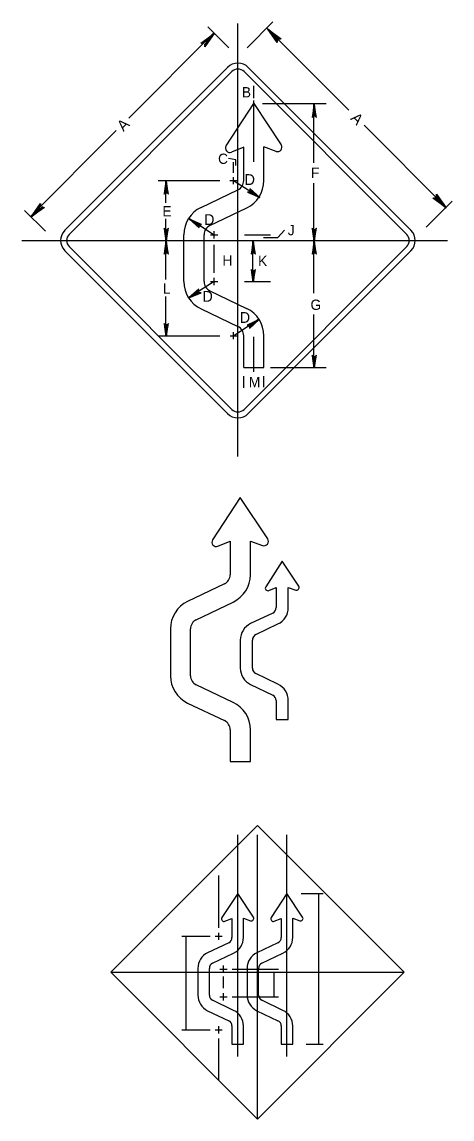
# Model space of a CAD drawing. Extents: x -0.124 to 0.191, y 0.004 to 0.276.
# Drawn here: x -0.1242 to -0.0247, y 0.0223 to 0.2759 of the extents above; entities that cross this region are included whole.
import ezdxf

# ---------------------------------------------------------------- set-up
doc = ezdxf.new("R2010")
doc.units = 0
doc.layers.add('1', color=7, linetype='Continuous')
doc.layers.add('3', color=7, linetype='Continuous')

# ---------------------------------------------------------------- blocks, each defined once
blk = doc.blocks.new('RARROW')
at = {"layer": '3'}
for p, q in [((-2.156, 0.28500000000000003), (-2.2665, 0.384625)), ((-2.2665, 0.384625), (0, 0)), ((0, 0), (-2.2665, -0.379125)), ((-2.156, 0.28500000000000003), (-2.075625, 0.12075)), ((0, 0), (-2.156, 0.28500000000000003)), ((-2.14975, -0.2705), (0, 0)), ((-2.075625, 0.12075), (0, 0)), ((0, 0), (-2.074, -0.108)), ((-2.2665, -0.379125), (-2.14975, -0.2705)), ((-2.074, -0.108), (-2.14975, -0.2705))]:
    blk.add_line(p, q, dxfattribs=at)

msp = doc.modelspace()

# ---------------------------------------------------------------- linework, layer by layer
at = {"layer": '1'}
for p, q in [((-0.07700190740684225, 0.24730114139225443), (-0.07061497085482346, 0.25708159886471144)), ((-0.07061497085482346, 0.25708159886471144), (-0.06426636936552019, 0.2475136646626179)), ((-0.07294829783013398, 0.24701153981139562), (-0.07577967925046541, 0.24583179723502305)), ((-0.07294829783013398, 0.23925057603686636), (-0.07294829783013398, 0.24701153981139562)), ((-0.06828164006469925, 0.23925057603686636), (-0.06828164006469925, 0.2470404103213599)), ((-0.06544031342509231, 0.24602565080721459), (-0.06828164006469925, 0.2470404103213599)), ((-0.07612017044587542, 0.23924826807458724), (-0.07445350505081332, 0.23924826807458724)), ((-0.07528683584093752, 0.23841493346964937), (-0.07528683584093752, 0.24008159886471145)), ((-0.08280441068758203, 0.23306196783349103), (-0.07427404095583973, 0.23714601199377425)), ((-0.08078922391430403, 0.22885283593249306), (-0.0722588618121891, 0.2329368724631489)), ((-0.08678163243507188, 0.2159133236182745), (-0.08678163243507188, 0.22674826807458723)), ((-0.08211496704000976, 0.21591331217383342), (-0.08211496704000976, 0.22674827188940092)), ((-0.08061496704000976, 0.22674826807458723), (-0.07894830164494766, 0.22674826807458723)), ((-0.07978163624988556, 0.22591493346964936), (-0.07978163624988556, 0.22758159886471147)), ((-0.08061496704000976, 0.21591493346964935), (-0.07894830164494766, 0.21591493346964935)), ((-0.07978163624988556, 0.21508159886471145), (-0.07978163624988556, 0.21674826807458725)), ((-0.08078842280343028, 0.21380836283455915), (-0.07226127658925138, 0.20972987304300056)), ((-0.08280199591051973, 0.20959846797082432), (-0.07427484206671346, 0.20551997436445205)), ((-0.07611478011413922, 0.20341493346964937), (-0.07444811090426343, 0.20341493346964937)), ((-0.07528144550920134, 0.20258159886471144), (-0.07528144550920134, 0.20424826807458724)), ((-0.07294829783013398, 0.19608159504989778), (-0.07294829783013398, 0.2034150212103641)), ((-0.06828164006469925, 0.19608159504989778), (-0.06828164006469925, 0.2034150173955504)), ((-0.07294829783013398, 0.19608159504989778), (-0.06828164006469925, 0.19608159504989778)), ((-0.07373907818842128, 0.1659831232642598), (-0.08012601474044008, 0.15620266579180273)), ((-0.06739047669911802, 0.1564151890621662), (-0.07373907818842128, 0.1659831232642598)), ((-0.07890378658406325, 0.15473332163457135), (-0.0760724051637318, 0.15591306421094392)), ((-0.0760724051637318, 0.15591306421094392), (-0.0760724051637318, 0.1481521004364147)), ((-0.07140574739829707, 0.1481521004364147), (-0.07140574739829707, 0.15594193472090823)), ((-0.07140574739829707, 0.15594193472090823), (-0.06856442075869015, 0.1549271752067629)), ((-0.06403025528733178, 0.1512579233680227), (-0.06786241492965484, 0.14538964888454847)), ((-0.06022109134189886, 0.14551716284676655), (-0.06403025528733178, 0.1512579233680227)), ((-0.07739814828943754, 0.14604753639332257), (-0.08592851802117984, 0.14196349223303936)), ((-0.06712907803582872, 0.14450804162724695), (-0.0654302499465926, 0.1452158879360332)), ((-0.0654302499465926, 0.1452158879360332), (-0.0654302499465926, 0.14055930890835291)), ((-0.06263025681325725, 0.14055930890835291), (-0.06263025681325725, 0.14523321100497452)), ((-0.06263025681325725, 0.14523321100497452), (-0.06092545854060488, 0.14462435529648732)), ((-0.08391333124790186, 0.1377543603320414), (-0.07538296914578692, 0.14183839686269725)), ((-0.06622569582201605, 0.13929657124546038), (-0.0713439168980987, 0.13684614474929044)), ((-0.08990573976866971, 0.13564979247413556), (-0.08990573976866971, 0.12481484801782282)), ((-0.0852390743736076, 0.12481483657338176), (-0.0852390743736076, 0.13564979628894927)), ((-0.07013480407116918, 0.1343206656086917), (-0.0650165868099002, 0.13677108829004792)), ((-0.07373025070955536, 0.13305792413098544), (-0.07373025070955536, 0.12655695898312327)), ((-0.07093024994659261, 0.1265569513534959), (-0.07093024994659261, 0.13305792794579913)), ((-0.06501803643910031, 0.12284688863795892), (-0.07013432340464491, 0.1252939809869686)), ((-0.07538538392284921, 0.1186313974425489), (-0.08391253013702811, 0.12270988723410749)), ((-0.07134246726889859, 0.1227680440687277), (-0.0662261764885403, 0.12032094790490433)), ((-0.08592610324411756, 0.11849999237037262), (-0.07739894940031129, 0.11442149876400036)), ((-0.0654302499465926, 0.11905797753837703), (-0.0654302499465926, 0.11465792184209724)), ((-0.06263025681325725, 0.11465792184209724), (-0.06263025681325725, 0.11905797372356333)), ((-0.0654302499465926, 0.11465792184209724), (-0.06263025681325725, 0.11465792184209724)), ((-0.0760724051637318, 0.11231654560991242), (-0.0760724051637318, 0.10498311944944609)), ((-0.07140574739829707, 0.10498311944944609), (-0.07140574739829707, 0.11231654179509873)), ((-0.0760724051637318, 0.10498311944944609), (-0.07140574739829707, 0.10498311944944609)), ((-0.07433316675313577, 0.07446970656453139), (-0.07797678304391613, 0.06889015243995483)), ((-0.07071141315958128, 0.06901139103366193), (-0.07433316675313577, 0.07446970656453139)), ((-0.06293316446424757, 0.07446970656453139), (-0.06657678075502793, 0.06889015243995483)), ((-0.059311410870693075, 0.06901139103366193), (-0.06293316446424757, 0.07446970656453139)), ((-0.07727952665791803, 0.06805191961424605), (-0.07566428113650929, 0.06872494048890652)), ((-0.07566428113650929, 0.06872494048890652), (-0.07566428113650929, 0.06429746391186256)), ((-0.07300204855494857, 0.06429746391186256), (-0.07300204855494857, 0.06874140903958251)), ((-0.07300204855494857, 0.06874140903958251), (-0.07138112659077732, 0.06816251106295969)), ((-0.06587952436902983, 0.06805191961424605), (-0.06426427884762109, 0.06872494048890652)), ((-0.06426427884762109, 0.06872494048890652), (-0.06426427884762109, 0.06429746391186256)), ((-0.06160204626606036, 0.06429746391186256), (-0.06160204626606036, 0.06874140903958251)), ((-0.06160204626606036, 0.06874140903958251), (-0.0599811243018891, 0.06816251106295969)), ((-0.0795664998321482, 0.06456970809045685), (-0.0778998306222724, 0.06456970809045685)), ((-0.07873316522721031, 0.06373637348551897), (-0.07873316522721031, 0.06540304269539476)), ((-0.07642059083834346, 0.06309685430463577), (-0.08128699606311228, 0.06076698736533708)), ((-0.06502058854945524, 0.06309685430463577), (-0.06988699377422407, 0.06076698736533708)), ((-0.08013737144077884, 0.058365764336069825), (-0.0752709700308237, 0.060695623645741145)), ((-0.06873736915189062, 0.058365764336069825), (-0.06387096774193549, 0.060695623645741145)), ((-0.08355592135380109, 0.05716514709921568), (-0.08355592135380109, 0.050984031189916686)), ((-0.08089368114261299, 0.05098402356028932), (-0.08089368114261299, 0.057165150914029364)), ((-0.07846650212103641, 0.05696970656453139), (-0.07679983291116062, 0.05696970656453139)), ((-0.07763316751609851, 0.0561363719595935), (-0.07763316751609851, 0.057803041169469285)), ((-0.07215591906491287, 0.05716514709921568), (-0.07215591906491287, 0.050984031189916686)), ((-0.06949367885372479, 0.05098402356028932), (-0.06949367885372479, 0.057165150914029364)), ((-0.07763316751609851, 0.049736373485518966), (-0.07763316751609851, 0.05140304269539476)), ((-0.0752723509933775, 0.04745649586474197), (-0.0801369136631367, 0.049783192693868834)), ((-0.07846650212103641, 0.05056970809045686), (-0.07679983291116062, 0.05056970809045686)), ((-0.06387234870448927, 0.04745649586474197), (-0.06873691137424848, 0.049783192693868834)), ((-0.08128561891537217, 0.047381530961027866), (-0.0764210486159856, 0.04505483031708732)), ((-0.06988561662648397, 0.047381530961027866), (-0.06502104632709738, 0.04505483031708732)), ((-0.07873316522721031, 0.0421363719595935), (-0.07873316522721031, 0.04380304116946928)), ((-0.07566428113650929, 0.04385399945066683), (-0.07566428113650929, 0.03967042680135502)), ((-0.07300204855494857, 0.03967042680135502), (-0.07300204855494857, 0.04385399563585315)), ((-0.06426427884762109, 0.04385399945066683), (-0.06426427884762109, 0.03967042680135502)), ((-0.06160204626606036, 0.03967042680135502), (-0.06160204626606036, 0.04385399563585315)), ((-0.0795664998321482, 0.04296970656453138), (-0.0778998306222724, 0.04296970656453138)), ((-0.07566428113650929, 0.03967042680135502), (-0.07300204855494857, 0.03967042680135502)), ((-0.06426427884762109, 0.03967042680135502), (-0.06160204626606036, 0.03967042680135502))]:
    msp.add_line(p, q, dxfattribs=at)
for centre, radius, start, end in [((-0.07616429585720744, 0.24675486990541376), 0.0009999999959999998, 146.8886580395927, 292.619864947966), ((-0.06510397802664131, 0.24696739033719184), 0.0009999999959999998, 250.34617594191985, 33.111341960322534), ((-0.07528163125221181, 0.23925057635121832), 0.002333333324, 295.58345846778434, 0), ((-0.07528163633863, 0.23925057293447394), 0.006999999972, 295.5834507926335, 0), ((-0.07978163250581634, 0.22674826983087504), 0.006999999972, 115.58345385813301, 180), ((-0.07978163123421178, 0.22674827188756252), 0.002333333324, 115.58343656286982, 180), ((-0.07978163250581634, 0.21591332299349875), 0.006999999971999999, 180.00000000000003, 244.43845176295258), ((-0.07978163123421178, 0.21591331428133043), 0.0023333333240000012, 180, 244.43846100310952), ((-0.07528163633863, 0.20341501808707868), 0.006999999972, 0, 64.4384641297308), ((-0.07528163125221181, 0.20341502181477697), 0.002333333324, 0, 64.43844982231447), ((-0.0792884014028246, 0.1556563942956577), 0.0009999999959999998, 146.8886580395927, 292.619864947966), ((-0.06822808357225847, 0.15586891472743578), 0.0009999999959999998, 250.34617594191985, 33.111341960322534), ((-0.07840573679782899, 0.14815210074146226), 0.002333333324, 295.58345819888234, 359.999999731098), ((-0.07840574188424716, 0.14815209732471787), 0.006999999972, 295.5834507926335, 0), ((-0.06735984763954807, 0.14506188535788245), 0.0005999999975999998, 146.8886580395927, 292.619864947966), ((-0.06072365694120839, 0.14518939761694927), 0.0005999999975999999, 250.34617594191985, 33.111341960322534), ((-0.0829057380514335, 0.13564979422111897), 0.006999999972, 115.58345385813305, 180), ((-0.06683024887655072, 0.14055930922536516), 0.0013999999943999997, 295.58345819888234, 359.999999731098), ((-0.06683025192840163, 0.1405593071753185), 0.0041999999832, 295.5834507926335, 0), ((-0.08290573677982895, 0.13564979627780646), 0.002333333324, 115.58343656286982, 180), ((-0.06953024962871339, 0.1330579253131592), 0.0041999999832, 115.58345385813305, 180), ((-0.06953024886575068, 0.1330579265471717), 0.0013999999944, 115.58343656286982, 180), ((-0.0829057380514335, 0.1248148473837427), 0.006999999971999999, 180.00000202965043, 244.438453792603), ((-0.08290573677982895, 0.12481483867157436), 0.0023333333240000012, 180, 244.43846100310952), ((-0.06953024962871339, 0.12655695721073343), 0.0041999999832, 180.00000202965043, 244.438453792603), ((-0.06953024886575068, 0.12655695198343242), 0.0013999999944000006, 180, 244.43846100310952), ((-0.06683025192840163, 0.11905797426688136), 0.0041999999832, 0, 64.4384641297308), ((-0.06683024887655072, 0.11905797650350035), 0.0013999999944, 0, 64.43844982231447), ((-0.07840574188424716, 0.1123165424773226), 0.006999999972, 0, 64.4384641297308), ((-0.07840573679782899, 0.1123165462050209), 0.002333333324, 0, 64.43844982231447), ((-0.07749894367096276, 0.06857851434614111), 0.0005704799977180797, 146.8886580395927, 292.619864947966), ((-0.07118925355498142, 0.06869975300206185), 0.0005704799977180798, 250.34617594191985, 33.111341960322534), ((-0.06609894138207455, 0.0685785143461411), 0.0005704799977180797, 146.8886580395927, 292.619864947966), ((-0.059789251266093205, 0.06869975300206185), 0.0005704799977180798, 250.34617594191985, 33.111341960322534), ((-0.0769954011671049, 0.06429746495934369), 0.0013311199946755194, 295.58345819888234, 359.999999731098), ((-0.07699540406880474, 0.06429746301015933), 0.003993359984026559, 295.5834507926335, 0), ((-0.06559539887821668, 0.06429746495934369), 0.0013311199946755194, 295.58345819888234, 359.999999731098), ((-0.06559540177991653, 0.06429746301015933), 0.003993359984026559, 295.5834507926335, 0), ((-0.07956256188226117, 0.05716514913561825), 0.00399335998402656, 115.58345385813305, 180), ((-0.07956256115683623, 0.05716515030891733), 0.0013311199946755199, 115.58343656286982, 180), ((-0.06816255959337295, 0.05716514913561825), 0.00399335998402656, 115.58345385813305, 180), ((-0.068162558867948, 0.05716515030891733), 0.0013311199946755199, 115.58343656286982, 180), ((-0.07956256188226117, 0.05098402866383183), 0.00399335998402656, 180.00000202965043, 244.438453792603), ((-0.07956256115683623, 0.050984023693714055), 0.0013311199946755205, 180, 244.43846100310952), ((-0.06816255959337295, 0.05098402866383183), 0.00399335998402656, 180.00000202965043, 244.438453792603), ((-0.068162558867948, 0.050984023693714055), 0.0013311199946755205, 180, 244.43846100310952), ((-0.07699540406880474, 0.0438539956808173), 0.00399335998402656, 0, 64.4384641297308), ((-0.06559540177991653, 0.0438539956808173), 0.00399335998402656, 0, 64.4384641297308), ((-0.0769954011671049, 0.04385399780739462), 0.0013311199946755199, 0, 64.43844982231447), ((-0.06559539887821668, 0.04385399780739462), 0.0013311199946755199, 0, 64.43844982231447)]:
    msp.add_arc(centre, radius, start, end, dxfattribs=at)
at = {"layer": '3'}
for p, q in [((-0.07640295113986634, 0.2699626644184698), (-0.08125049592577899, 0.2748102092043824)), ((-0.07428163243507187, 0.17549417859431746), (-0.07428163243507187, 0.2755808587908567)), ((-0.07216031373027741, 0.2699626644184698), (-0.06618582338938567, 0.27593715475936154)), ((-0.048600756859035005, 0.25552366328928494), (-0.06760003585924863, 0.2745229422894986)), ((-0.09954346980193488, 0.2536888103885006), (-0.07983628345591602, 0.2733959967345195)), ((-0.11430388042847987, 0.22781909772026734), (-0.07668579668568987, 0.26543718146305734)), ((-0.11331393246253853, 0.22682914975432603), (-0.07569584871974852, 0.26444723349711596)), ((-0.07286741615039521, 0.26444723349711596), (-0.035249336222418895, 0.22682914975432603)), ((-0.07187746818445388, 0.26543718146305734), (-0.034259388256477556, 0.22781909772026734)), ((-0.07061497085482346, 0.25835239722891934), (-0.07061497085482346, 0.26113980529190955)), ((-0.07061497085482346, 0.24362069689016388), (-0.07061497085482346, 0.2577889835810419)), ((-0.06861497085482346, 0.25708159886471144), (-0.053898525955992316, 0.25708159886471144)), ((-0.05669852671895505, 0.24339406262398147), (-0.05669852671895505, 0.25708159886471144)), ((-0.026163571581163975, 0.23308648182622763), (-0.0451190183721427, 0.25204192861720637)), ((-0.12226269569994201, 0.23096958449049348), (-0.10241965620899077, 0.25081262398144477)), ((-0.07528683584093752, 0.24108159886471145), (-0.07528683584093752, 0.24353714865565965)), ((-0.07428148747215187, 0.24108159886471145), (-0.07428148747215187, 0.24353714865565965)), ((-0.09272814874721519, 0.23924826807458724), (-0.07844830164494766, 0.23924826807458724)), ((-0.09096546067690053, 0.23414406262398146), (-0.09096546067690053, 0.23924826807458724)), ((-0.07528683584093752, 0.23924826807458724), (-0.0693588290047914, 0.23551958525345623)), ((-0.05669852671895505, 0.22541493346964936), (-0.05669852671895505, 0.23865409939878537)), ((-0.030723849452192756, 0.22852620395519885), (-0.024749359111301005, 0.23450069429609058)), ((-0.11882936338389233, 0.22753625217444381), (-0.12367690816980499, 0.23238379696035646)), ((-0.09096546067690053, 0.22541493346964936), (-0.09096546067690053, 0.23039406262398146)), ((-0.08565583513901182, 0.23055534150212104), (-0.07978163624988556, 0.22674826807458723)), ((-0.07278163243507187, 0.22674826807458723), (-0.06678163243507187, 0.22674826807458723)), ((-0.1242442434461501, 0.22541493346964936), (-0.025800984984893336, 0.22541493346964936)), ((-0.07569584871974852, 0.18638263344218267), (-0.11331393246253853, 0.2240007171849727)), ((-0.09096546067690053, 0.21639406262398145), (-0.09096546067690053, 0.22541493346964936)), ((-0.07978163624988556, 0.21791493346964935), (-0.07978163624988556, 0.22441493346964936)), ((-0.035249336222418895, 0.2240007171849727), (-0.07286741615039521, 0.18638263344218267)), ((-0.07278163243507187, 0.2254204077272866), (-0.06678163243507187, 0.2254204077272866)), ((-0.07084651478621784, 0.21591493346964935), (-0.07084651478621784, 0.22541493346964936)), ((-0.05669852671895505, 0.21326906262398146), (-0.05669852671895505, 0.22541493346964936)), ((-0.07668579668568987, 0.18539268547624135), (-0.11430388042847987, 0.22301076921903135)), ((-0.034259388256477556, 0.22301076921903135), (-0.07187746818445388, 0.18539268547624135)), ((-0.08574892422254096, 0.2122538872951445), (-0.07980275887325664, 0.21600279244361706)), ((-0.07278163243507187, 0.21591493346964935), (-0.06678163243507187, 0.21591493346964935)), ((-0.09096546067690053, 0.20341493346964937), (-0.09096546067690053, 0.21247207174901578)), ((-0.05669852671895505, 0.19608159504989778), (-0.05669852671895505, 0.2083384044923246)), ((-0.07528144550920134, 0.20341493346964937), (-0.0694493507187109, 0.20728599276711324)), ((-0.09272814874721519, 0.20341493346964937), (-0.07844830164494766, 0.20341493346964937)), ((-0.07061497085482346, 0.1950923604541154), (-0.07061497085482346, 0.20314923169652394)), ((-0.06678164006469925, 0.19608159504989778), (-0.053898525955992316, 0.19608159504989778)), ((-0.07294829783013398, 0.19139406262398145), (-0.07294829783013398, 0.19408159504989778)), ((-0.06828164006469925, 0.19151906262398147), (-0.06828164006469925, 0.19408159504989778)), ((-0.10367429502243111, 0.056269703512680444), (-0.0697331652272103, 0.09021083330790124)), ((-0.0697331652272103, 0.09021083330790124), (-0.03579203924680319, 0.056269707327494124)), ((-0.07433316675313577, 0.03682016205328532), (-0.07433316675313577, 0.08799531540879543)), ((-0.0697331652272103, 0.02232857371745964), (-0.0697331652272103, 0.08799531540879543)), ((-0.06293316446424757, 0.03682016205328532), (-0.06293316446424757, 0.08799531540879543)), ((-0.07873316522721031, 0.06656970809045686), (-0.07873316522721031, 0.0786478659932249)), ((-0.05965317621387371, 0.07446970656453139), (-0.054543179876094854, 0.07446970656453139)), ((-0.055543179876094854, 0.03966970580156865), (-0.055543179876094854, 0.07446970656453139)), ((-0.08724622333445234, 0.06456970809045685), (-0.08073316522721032, 0.06456970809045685)), ((-0.08624622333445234, 0.04296970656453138), (-0.08624622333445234, 0.06456970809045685)), ((-0.1036742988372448, 0.056269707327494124), (-0.03579203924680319, 0.056269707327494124)), ((-0.10367429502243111, 0.056269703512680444), (-0.06973316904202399, 0.022328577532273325)), ((-0.07563316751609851, 0.05696970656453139), (-0.06493316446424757, 0.05696970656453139)), ((-0.06973316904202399, 0.022328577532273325), (-0.03579203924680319, 0.056269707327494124)), ((-0.06593316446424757, 0.05056970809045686), (-0.06593316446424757, 0.056269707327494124)), ((-0.07763316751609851, 0.052569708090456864), (-0.07763316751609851, 0.05526970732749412)), ((-0.07563316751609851, 0.05056970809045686), (-0.06493316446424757, 0.05056970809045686)), ((-0.08724622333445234, 0.04296970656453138), (-0.08073316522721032, 0.04296970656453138)), ((-0.07873316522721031, 0.03132857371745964), (-0.07873316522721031, 0.04096970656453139)), ((-0.05852817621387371, 0.03966970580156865), (-0.054543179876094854, 0.03966970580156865))]:
    msp.add_line(p, q, dxfattribs=at)
for points in [[(-0.07479325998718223, 0.242766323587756), (-0.07479325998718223, 0.24406741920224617), (-0.0764751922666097, 0.24433688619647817)], [(-0.06837458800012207, 0.22612398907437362), (-0.0650439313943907, 0.22612398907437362), (-0.06351362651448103, 0.22783445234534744)]]:
    msp.add_lwpolyline(points, dxfattribs=at)
for centre, radius, start, end in [((-0.07428162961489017, 0.26303301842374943), 0.0034, 44.99999742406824, 135), ((-0.07428162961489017, 0.26303301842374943), 0.002, 44.99999742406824, 135), ((-0.11189971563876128, 0.22541493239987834), 0.0034, 135.00000000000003, 225.00000000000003), ((-0.11189971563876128, 0.22541493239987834), 0.002, 135.00000000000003, 225.00000000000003), ((-0.036663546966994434, 0.22541493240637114), 0.002, 315.0000025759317, 44.99999726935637), ((-0.036663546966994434, 0.22541493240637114), 0.0034000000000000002, 315.0000025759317, 44.99999726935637), ((-0.07428162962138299, 0.18779684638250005), 0.0034000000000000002, 225, 315.00000273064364), ((-0.07428162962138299, 0.18779684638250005), 0.002, 225, 315.00000273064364)]:
    msp.add_arc(centre, radius, start, end, dxfattribs=at)

# ---------------------------------------------------------------- block references
for p, xscale, yscale, rotation in [((-0.067375, 0.27425), 0.0016545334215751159, 0.0016366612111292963, 135.00000000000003), ((-0.07975, 0.27325), 0.0016545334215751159, 0.0016366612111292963, 44.999999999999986), ((-0.056625, 0.256875), 0.0013236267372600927, -0.001309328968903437, 90), ((-0.090875, 0.239125), 0.0013236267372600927, -0.001309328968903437, 90), ((-0.06925, 0.235375), 0.0013236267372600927, -0.0013093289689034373, -32.937747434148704), ((-0.026125, 0.233), 0.0016545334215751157, 0.001636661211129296, -45), ((-0.122125, 0.230875), 0.001654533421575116, 0.001636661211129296, -135), ((-0.0855, 0.230375), 0.0013236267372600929, -0.001309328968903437, 146.65790015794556), ((-0.090875, 0.22525), 0.0013236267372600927, -0.001309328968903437, -90), ((-0.056625, 0.22525), 0.0013236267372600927, -0.001309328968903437, -90), ((-0.090875, 0.22525), 0.0013236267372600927, -0.001309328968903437, 90), ((-0.07075000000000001, 0.22525), 0.0013236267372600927, -0.001309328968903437, 90), ((-0.056625, 0.22525), 0.0013236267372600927, -0.001309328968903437, 90), ((-0.07075000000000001, 0.21575), 0.0013236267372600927, -0.001309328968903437, -90), ((-0.085625, 0.212125), 0.0013236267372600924, -0.001309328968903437, -147.979386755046), ((-0.090875, 0.20325000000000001), 0.0013236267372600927, -0.001309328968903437, -90), ((-0.069375, 0.207125), 0.0013236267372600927, -0.0013093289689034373, 33.673578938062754), ((-0.056625, 0.195875), 0.0013236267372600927, -0.001309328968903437, -90)]:
    msp.add_blockref('RARROW', p, dxfattribs=dict(at, xscale=xscale, yscale=yscale, rotation=rotation))

# ---------------------------------------------------------------- texts
for s, height, p in [('B', 0.0023752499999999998, (-0.073375, 0.2585)), ('C', 0.0023752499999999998, (-0.078875, 0.243125)), ('F', 0.0023752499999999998, (-0.057375, 0.239875)), ('D', 0.0024997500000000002, (-0.07275, 0.23825000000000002)), ('E', 0.0023752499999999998, (-0.09175, 0.231)), ('D', 0.0024997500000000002, (-0.082125, 0.229)), ('J', 0.0023752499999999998, (-0.06275, 0.226625)), ('H', 0.0023752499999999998, (-0.077875, 0.21962500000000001)), ('K', 0.0023752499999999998, (-0.069625, 0.2195)), ('L', 0.0023752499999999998, (-0.091625, 0.213125)), ('D', 0.0024997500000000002, (-0.0825, 0.21125)), ('G', 0.0023752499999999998, (-0.0575, 0.209375)), ('D', 0.0024997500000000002, (-0.073875, 0.206375)), ('M', 0.0023752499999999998, (-0.07175000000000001, 0.1915))]:
    msp.add_text(s, height=height, dxfattribs=at).set_placement(p)
for rotation, p in [(315, (-0.048375, 0.2535)), (45, (-0.10075, 0.2505))]:
    msp.add_text('A', height=0.0024997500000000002, rotation=rotation, dxfattribs=at).set_placement(p)

doc.saveas('drawing.dxf')
